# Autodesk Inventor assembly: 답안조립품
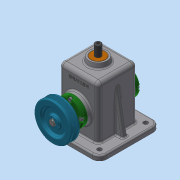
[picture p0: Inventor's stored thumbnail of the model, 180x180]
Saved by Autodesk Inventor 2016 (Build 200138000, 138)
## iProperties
Created: 2022-11
Part Number: 답안조립품
Material: 일반
Document SubType Name: Assembly
Designer: PC-1-2
Author: PC-1-2
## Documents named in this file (15)
- C:\Users\PC-1-2\Desktop\721106V1015\답안조립품.iam
- C:\Users\PC-1-2\Desktop\721106V1015\본체.ipt
- C:\Users\PC-1-2\Desktop\721106V1015\앞커버.ipt
- C:\Users\PC-1-2\Desktop\721106V1015\뒤커버.ipt
- C:\Users\PC-1-2\Desktop\721106V1015\오일실 12 25 7.ipt
- C:\Users\PC-1-2\Desktop\721106V1015\베어링 6201.ipt
- C:\Users\PC-1-2\Desktop\721106V1015\편심축.ipt
- C:\Users\PC-1-2\Desktop\721106V1015\키 4 x 4 x 15.ipt
- C:\Users\PC-1-2\Desktop\721106V1015\V벨트풀리.ipt
- C:\Users\PC-1-2\Desktop\721106V1015\부시.ipt
- C:\Users\PC-1-2\Desktop\721106V1015\링크.ipt
- C:\Users\PC-1-2\Desktop\721106V1015\슬라이드.ipt
- C:\Users\PC-1-2\Desktop\721106V1015\핀 5 x 18.ipt
- C:\Users\PC-1-2\Desktop\721106V1015\고정핀 1.2 x 10.ipt
- C:\Users\PC-1-2\Desktop\721106V1015\볼트 M4 x 12.ipt
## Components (12 placed, 4 different names)
1. V벨트풀리:1
2. 핀 5 x 18:1
3. 고정핀 1.2 x 10:1
4. 고정핀 1.2 x 10:2
5. ISO 4762 M4 x 12:1
6. ISO 4762 M4 x 12:3
7. ISO 4762 M4 x 12:4
8. ISO 4762 M4 x 12:5
9. ISO 4762 M4 x 12:2
10. ISO 4762 M4 x 12:6
11. ISO 4762 M4 x 12:7
12. ISO 4762 M4 x 12:8
